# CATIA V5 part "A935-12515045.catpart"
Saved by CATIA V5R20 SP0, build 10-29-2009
Part number: A935-12515045
Source: Unknown
Property "A": "85.000"
Property "ARTICLENO": "A935-12515045"
Property "B": "30.000"
Property "BOMINFO": "A935-12515045"
Property "CODE": "A935-12515045"
Property "L": "150.000"
Property "L1": "127.860"
Property "LINA": "A935-12515045"
Property "NB": "A935-12515045"
Property "NBSYN": "$CODE."
Property "NN": "A935"
Property "NT": "VDI 3357 H-Type Cam Drivers, steel (16MnCr5)"
Property "SUPPLIER": "CF"
Property "T": "45.000"
Property "W": "125.000"
Bounding box of the stored display mesh (mm): x 0 to 150, y 0 to 45, z -125 to 0
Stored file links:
  C:\Users\Utente\Desktop\3D files A935\A935-12515045.catpart
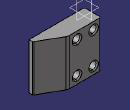
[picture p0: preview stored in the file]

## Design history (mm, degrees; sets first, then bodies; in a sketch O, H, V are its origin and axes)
Body1 "Geometry.1" (main body)
  Solid1 "A935-12515045.catpart": solid without history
